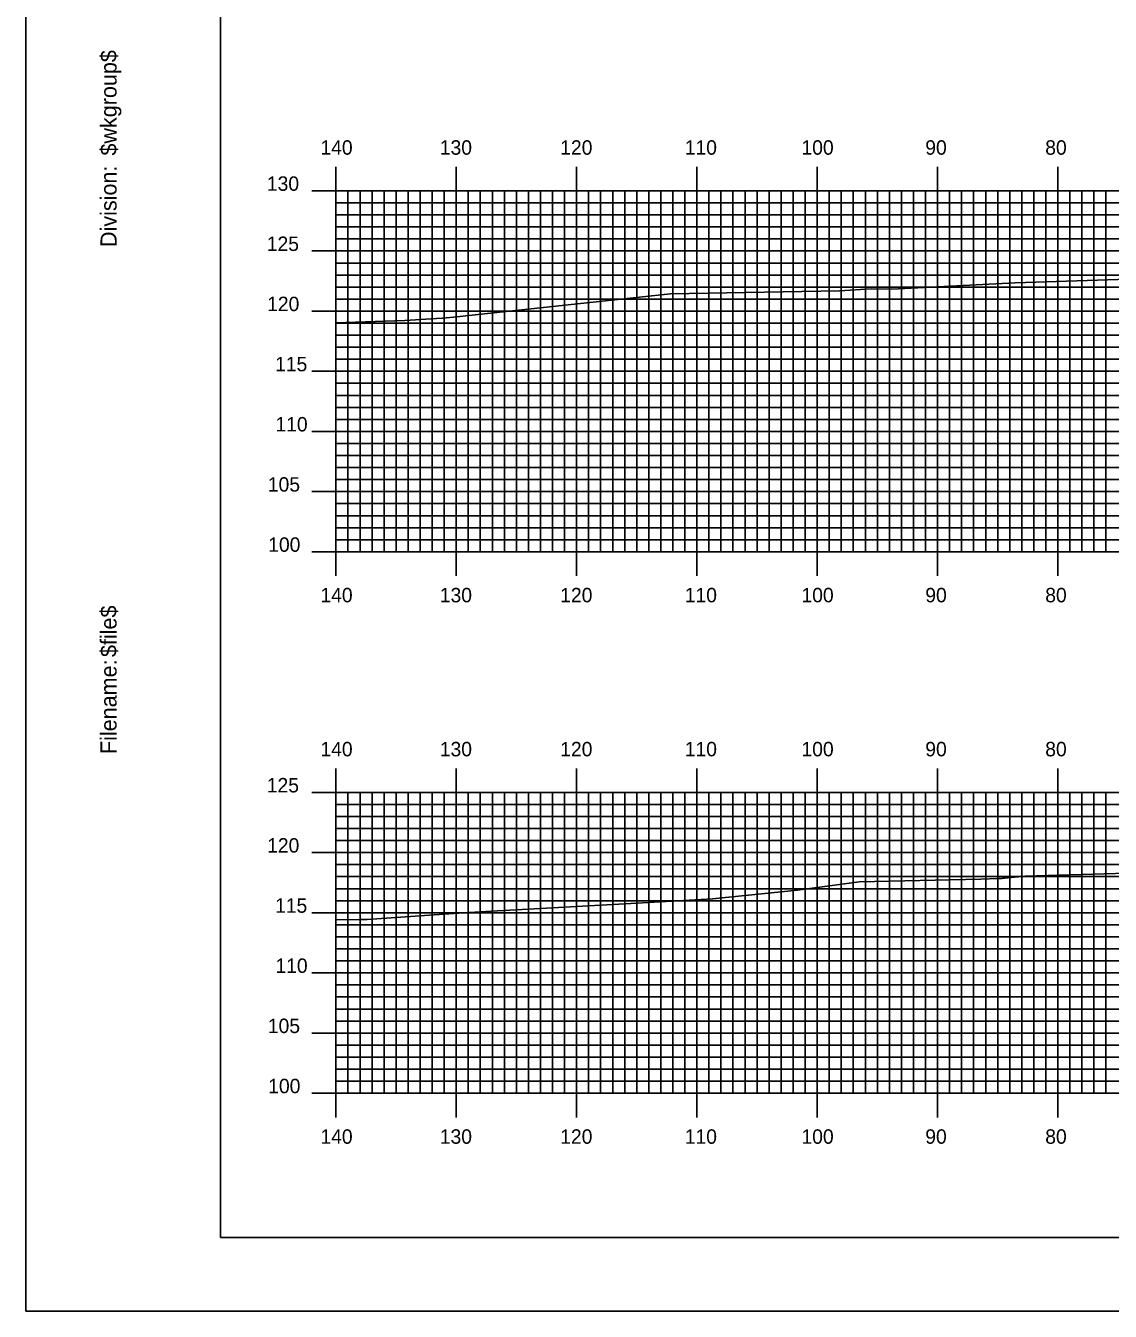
# Model space of a CAD drawing. Extents: x 1766907 to 1767250, y 442591 to 442811.
# Drawn here: x 1766906.6 to 1766996.8, y 442590.5 to 442697.4 of the extents above; entities that cross this region are included whole.
import ezdxf

# ---------------------------------------------------------------- set-up
doc = ezdxf.new("R2010")
doc.units = 0
for name, color, linetype in [('BORDER', 7, 'Continuous'), ('H_V ANNOTATION', 7, 'Continuous'), ('MAJOR', 7, 'Continuous'), ('MINOR', 7, 'Continuous'), ('PLOT BOUNDARY', 7, 'Continuous'), ('S_Roadway_Centerline', 7, 'Continuous')]:
    doc.layers.add(name, color=color, linetype=linetype)

msp = doc.modelspace()

# ---------------------------------------------------------------- linework, layer by layer
at = {"layer": 'BORDER'}
msp.add_lwpolyline([(1766922.82, 442596.67), (1767242.82, 442596.67), (1767242.82, 442806.67), (1766922.82, 442806.67)], close=True, dxfattribs=at)
at = {"layer": 'MAJOR'}
for p, q in [((1766932.42, 442685.67), (1766932.42, 442683.67)), ((1766942.42, 442685.67), (1766942.42, 442683.67)), ((1766952.42, 442685.67), (1766952.42, 442683.67)), ((1766962.42, 442685.67), (1766962.42, 442683.67)), ((1766972.42, 442685.67), (1766972.42, 442683.67)), ((1766982.42, 442685.67), (1766982.42, 442683.67)), ((1766992.42, 442685.67), (1766992.42, 442683.67)), ((1766930.42, 442683.67), (1766932.42, 442683.67)), ((1766932.42, 442683.67), (1767212.42, 442683.67)), ((1766932.42, 442653.67), (1766932.42, 442683.67)), ((1766932.42, 442653.67), (1766932.42, 442683.67)), ((1766932.42, 442683.67), (1767212.42, 442683.67)), ((1766942.42, 442653.67), (1766942.42, 442683.67)), ((1766952.42, 442653.67), (1766952.42, 442683.67)), ((1766962.42, 442653.67), (1766962.42, 442683.67)), ((1766972.42, 442653.67), (1766972.42, 442683.67)), ((1766982.42, 442653.67), (1766982.42, 442683.67)), ((1766992.42, 442653.67), (1766992.42, 442683.67)), ((1766930.42, 442678.67), (1766932.42, 442678.67)), ((1766932.42, 442678.67), (1767212.42, 442678.67)), ((1766930.42, 442673.67), (1766932.42, 442673.67)), ((1766932.42, 442673.67), (1767212.42, 442673.67)), ((1766930.42, 442668.67), (1766932.42, 442668.67)), ((1766932.42, 442668.67), (1767212.42, 442668.67)), ((1766930.42, 442663.67), (1766932.42, 442663.67)), ((1766932.42, 442663.67), (1767212.42, 442663.67)), ((1766930.42, 442658.67), (1766932.42, 442658.67)), ((1766932.42, 442658.67), (1767212.42, 442658.67)), ((1766930.42, 442653.67), (1766932.42, 442653.67)), ((1766932.42, 442653.67), (1767212.42, 442653.67)), ((1766932.42, 442653.67), (1767212.42, 442653.67)), ((1766932.42, 442651.66), (1766932.42, 442653.67)), ((1766942.42, 442651.66), (1766942.42, 442653.67)), ((1766952.42, 442651.66), (1766952.42, 442653.67)), ((1766962.42, 442651.66), (1766962.42, 442653.67)), ((1766972.42, 442651.66), (1766972.42, 442653.67)), ((1766982.42, 442651.66), (1766982.42, 442653.67)), ((1766992.42, 442651.66), (1766992.42, 442653.67)), ((1766932.42, 442635.67), (1766932.42, 442633.67)), ((1766942.42, 442635.67), (1766942.42, 442633.67)), ((1766952.42, 442635.67), (1766952.42, 442633.67)), ((1766962.42, 442635.67), (1766962.42, 442633.67)), ((1766972.42, 442635.67), (1766972.42, 442633.67)), ((1766982.42, 442635.67), (1766982.42, 442633.67)), ((1766992.42, 442635.67), (1766992.42, 442633.67)), ((1766930.42, 442633.67), (1766932.42, 442633.67)), ((1766932.42, 442633.67), (1767212.42, 442633.67)), ((1766932.42, 442608.67), (1766932.42, 442633.67)), ((1766932.42, 442608.67), (1766932.42, 442633.67)), ((1766932.42, 442633.67), (1767212.42, 442633.67)), ((1766942.42, 442608.67), (1766942.42, 442633.67)), ((1766952.42, 442608.67), (1766952.42, 442633.67)), ((1766962.42, 442608.67), (1766962.42, 442633.67)), ((1766972.42, 442608.67), (1766972.42, 442633.67)), ((1766982.42, 442608.67), (1766982.42, 442633.67)), ((1766992.42, 442608.67), (1766992.42, 442633.67)), ((1766930.42, 442628.67), (1766932.42, 442628.67)), ((1766932.42, 442628.67), (1767212.42, 442628.67)), ((1766930.42, 442623.67), (1766932.42, 442623.67)), ((1766932.42, 442623.67), (1767212.42, 442623.67)), ((1766930.42, 442618.67), (1766932.42, 442618.67)), ((1766932.42, 442618.67), (1767212.42, 442618.67)), ((1766930.42, 442613.67), (1766932.42, 442613.67)), ((1766932.42, 442613.67), (1767212.42, 442613.67)), ((1766930.42, 442608.67), (1766932.42, 442608.67)), ((1766932.42, 442608.67), (1767212.42, 442608.67)), ((1766932.42, 442608.67), (1767212.42, 442608.67)), ((1766932.42, 442606.66), (1766932.42, 442608.67)), ((1766942.42, 442606.66), (1766942.42, 442608.67)), ((1766952.42, 442606.66), (1766952.42, 442608.67)), ((1766962.42, 442606.66), (1766962.42, 442608.67)), ((1766972.42, 442606.66), (1766972.42, 442608.67)), ((1766982.42, 442606.66), (1766982.42, 442608.67)), ((1766992.42, 442606.66), (1766992.42, 442608.67))]:
    msp.add_line(p, q, dxfattribs=at)
at = {"layer": 'MINOR'}
for p, q in [((1766933.42, 442653.67), (1766933.42, 442683.67)), ((1766934.42, 442653.67), (1766934.42, 442683.67)), ((1766935.42, 442653.67), (1766935.42, 442683.67)), ((1766936.42, 442653.67), (1766936.42, 442683.67)), ((1766937.42, 442653.67), (1766937.42, 442683.67)), ((1766938.42, 442653.67), (1766938.42, 442683.67)), ((1766939.42, 442653.67), (1766939.42, 442683.67)), ((1766940.42, 442653.67), (1766940.42, 442683.67)), ((1766941.42, 442653.67), (1766941.42, 442683.67)), ((1766943.42, 442653.67), (1766943.42, 442683.67)), ((1766944.42, 442653.67), (1766944.42, 442683.67)), ((1766945.42, 442653.67), (1766945.42, 442683.67)), ((1766946.42, 442653.67), (1766946.42, 442683.67)), ((1766947.42, 442653.67), (1766947.42, 442683.67)), ((1766948.42, 442653.67), (1766948.42, 442683.67)), ((1766949.42, 442653.67), (1766949.42, 442683.67)), ((1766950.42, 442653.67), (1766950.42, 442683.67)), ((1766951.42, 442653.67), (1766951.42, 442683.67)), ((1766953.42, 442653.67), (1766953.42, 442683.67)), ((1766954.42, 442653.67), (1766954.42, 442683.67)), ((1766955.42, 442653.67), (1766955.42, 442683.67)), ((1766956.42, 442653.67), (1766956.42, 442683.67)), ((1766957.42, 442653.67), (1766957.42, 442683.67)), ((1766958.42, 442653.67), (1766958.42, 442683.67)), ((1766959.42, 442653.67), (1766959.42, 442683.67)), ((1766960.42, 442653.67), (1766960.42, 442683.67)), ((1766961.42, 442653.67), (1766961.42, 442683.67)), ((1766963.42, 442653.67), (1766963.42, 442683.67)), ((1766964.42, 442653.67), (1766964.42, 442683.67)), ((1766965.42, 442653.67), (1766965.42, 442683.67)), ((1766966.42, 442653.67), (1766966.42, 442683.67)), ((1766967.42, 442653.67), (1766967.42, 442683.67)), ((1766968.42, 442653.67), (1766968.42, 442683.67)), ((1766969.42, 442653.67), (1766969.42, 442683.67)), ((1766970.42, 442653.67), (1766970.42, 442683.67)), ((1766971.42, 442653.67), (1766971.42, 442683.67)), ((1766973.42, 442653.67), (1766973.42, 442683.67)), ((1766974.42, 442653.67), (1766974.42, 442683.67)), ((1766975.42, 442653.67), (1766975.42, 442683.67)), ((1766976.42, 442653.67), (1766976.42, 442683.67)), ((1766977.42, 442653.67), (1766977.42, 442683.67)), ((1766978.42, 442653.67), (1766978.42, 442683.67)), ((1766979.42, 442653.67), (1766979.42, 442683.67)), ((1766980.42, 442653.67), (1766980.42, 442683.67)), ((1766981.42, 442653.67), (1766981.42, 442683.67)), ((1766983.42, 442653.67), (1766983.42, 442683.67)), ((1766984.42, 442653.67), (1766984.42, 442683.67)), ((1766985.42, 442653.67), (1766985.42, 442683.67)), ((1766986.42, 442653.67), (1766986.42, 442683.67)), ((1766987.42, 442653.67), (1766987.42, 442683.67)), ((1766988.42, 442653.67), (1766988.42, 442683.67)), ((1766989.42, 442653.67), (1766989.42, 442683.67)), ((1766990.42, 442653.67), (1766990.42, 442683.67)), ((1766991.42, 442653.67), (1766991.42, 442683.67)), ((1766993.42, 442653.67), (1766993.42, 442683.67)), ((1766994.42, 442653.67), (1766994.42, 442683.67)), ((1766995.42, 442653.67), (1766995.42, 442683.67)), ((1766996.42, 442653.67), (1766996.42, 442683.67)), ((1766932.42, 442682.67), (1767212.42, 442682.67)), ((1766932.42, 442682.67), (1766934.43, 442682.67)), ((1766932.42, 442681.67), (1767212.42, 442681.67)), ((1766932.42, 442681.67), (1766934.43, 442681.67)), ((1766932.42, 442680.67), (1767212.42, 442680.67)), ((1766932.42, 442680.67), (1766934.43, 442680.67)), ((1766932.42, 442679.67), (1767212.42, 442679.67)), ((1766932.42, 442679.67), (1766934.43, 442679.67)), ((1766932.42, 442677.67), (1767212.42, 442677.67)), ((1766932.42, 442677.67), (1766934.43, 442677.67)), ((1766932.42, 442676.67), (1767212.42, 442676.67)), ((1766932.42, 442676.67), (1766934.43, 442676.67)), ((1766932.42, 442675.67), (1767212.42, 442675.67)), ((1766932.42, 442675.67), (1766934.43, 442675.67)), ((1766932.42, 442674.67), (1767212.42, 442674.67)), ((1766932.42, 442674.67), (1766934.43, 442674.67)), ((1766932.42, 442672.67), (1767212.42, 442672.67)), ((1766932.42, 442672.67), (1766934.43, 442672.67)), ((1766932.42, 442671.67), (1767212.42, 442671.67)), ((1766932.42, 442671.67), (1766934.43, 442671.67)), ((1766932.42, 442670.67), (1767212.42, 442670.67)), ((1766932.42, 442670.67), (1766934.43, 442670.67)), ((1766932.42, 442669.67), (1767212.42, 442669.67)), ((1766932.42, 442669.67), (1766934.43, 442669.67)), ((1766932.42, 442667.67), (1767212.42, 442667.67)), ((1766932.42, 442667.67), (1766934.43, 442667.67)), ((1766932.42, 442666.67), (1767212.42, 442666.67)), ((1766932.42, 442666.67), (1766934.43, 442666.67)), ((1766932.42, 442665.67), (1767212.42, 442665.67)), ((1766932.42, 442665.67), (1766934.43, 442665.67)), ((1766932.42, 442664.67), (1767212.42, 442664.67)), ((1766932.42, 442664.67), (1766934.43, 442664.67)), ((1766932.42, 442662.67), (1767212.42, 442662.67)), ((1766932.42, 442662.67), (1766934.43, 442662.67)), ((1766932.42, 442661.67), (1767212.42, 442661.67)), ((1766932.42, 442661.67), (1766934.43, 442661.67)), ((1766932.42, 442660.67), (1767212.42, 442660.67)), ((1766932.42, 442660.67), (1766934.43, 442660.67)), ((1766932.42, 442659.67), (1767212.42, 442659.67)), ((1766932.42, 442659.67), (1766934.43, 442659.67)), ((1766932.42, 442657.67), (1767212.42, 442657.67)), ((1766932.42, 442657.67), (1766934.43, 442657.67)), ((1766932.42, 442656.67), (1767212.42, 442656.67)), ((1766932.42, 442656.67), (1766934.43, 442656.67)), ((1766932.42, 442655.67), (1767212.42, 442655.67)), ((1766932.42, 442655.67), (1766934.43, 442655.67)), ((1766932.42, 442654.67), (1767212.42, 442654.67)), ((1766932.42, 442654.67), (1766934.43, 442654.67)), ((1766933.42, 442608.67), (1766933.42, 442633.67)), ((1766934.42, 442608.67), (1766934.42, 442633.67)), ((1766935.42, 442608.67), (1766935.42, 442633.67)), ((1766936.42, 442608.67), (1766936.42, 442633.67)), ((1766937.42, 442608.67), (1766937.42, 442633.67)), ((1766938.42, 442608.67), (1766938.42, 442633.67)), ((1766939.42, 442608.67), (1766939.42, 442633.67)), ((1766940.42, 442608.67), (1766940.42, 442633.67)), ((1766941.42, 442608.67), (1766941.42, 442633.67)), ((1766943.42, 442608.67), (1766943.42, 442633.67)), ((1766944.42, 442608.67), (1766944.42, 442633.67)), ((1766945.42, 442608.67), (1766945.42, 442633.67)), ((1766946.42, 442608.67), (1766946.42, 442633.67)), ((1766947.42, 442608.67), (1766947.42, 442633.67)), ((1766948.42, 442608.67), (1766948.42, 442633.67)), ((1766949.42, 442608.67), (1766949.42, 442633.67)), ((1766950.42, 442608.67), (1766950.42, 442633.67)), ((1766951.42, 442608.67), (1766951.42, 442633.67)), ((1766953.42, 442608.67), (1766953.42, 442633.67)), ((1766954.42, 442608.67), (1766954.42, 442633.67)), ((1766955.42, 442608.67), (1766955.42, 442633.67)), ((1766956.42, 442608.67), (1766956.42, 442633.67)), ((1766957.42, 442608.67), (1766957.42, 442633.67)), ((1766958.42, 442608.67), (1766958.42, 442633.67)), ((1766959.42, 442608.67), (1766959.42, 442633.67)), ((1766960.42, 442608.67), (1766960.42, 442633.67)), ((1766961.42, 442608.67), (1766961.42, 442633.67)), ((1766963.42, 442608.67), (1766963.42, 442633.67)), ((1766964.42, 442608.67), (1766964.42, 442633.67)), ((1766965.42, 442608.67), (1766965.42, 442633.67)), ((1766966.42, 442608.67), (1766966.42, 442633.67)), ((1766967.42, 442608.67), (1766967.42, 442633.67)), ((1766968.42, 442608.67), (1766968.42, 442633.67)), ((1766969.42, 442608.67), (1766969.42, 442633.67)), ((1766970.42, 442608.67), (1766970.42, 442633.67)), ((1766971.42, 442608.67), (1766971.42, 442633.67)), ((1766973.42, 442608.67), (1766973.42, 442633.67)), ((1766974.42, 442608.67), (1766974.42, 442633.67)), ((1766975.42, 442608.67), (1766975.42, 442633.67)), ((1766976.42, 442608.67), (1766976.42, 442633.67)), ((1766977.42, 442608.67), (1766977.42, 442633.67)), ((1766978.42, 442608.67), (1766978.42, 442633.67)), ((1766979.42, 442608.67), (1766979.42, 442633.67)), ((1766980.42, 442608.67), (1766980.42, 442633.67)), ((1766981.42, 442608.67), (1766981.42, 442633.67)), ((1766983.42, 442608.67), (1766983.42, 442633.67)), ((1766984.42, 442608.67), (1766984.42, 442633.67)), ((1766985.42, 442608.67), (1766985.42, 442633.67)), ((1766986.42, 442608.67), (1766986.42, 442633.67)), ((1766987.42, 442608.67), (1766987.42, 442633.67)), ((1766988.42, 442608.67), (1766988.42, 442633.67)), ((1766989.42, 442608.67), (1766989.42, 442633.67)), ((1766990.42, 442608.67), (1766990.42, 442633.67)), ((1766991.42, 442608.67), (1766991.42, 442633.67)), ((1766993.42, 442608.67), (1766993.42, 442633.67)), ((1766994.42, 442608.67), (1766994.42, 442633.67)), ((1766995.42, 442608.67), (1766995.42, 442633.67)), ((1766996.42, 442608.67), (1766996.42, 442633.67)), ((1766932.42, 442632.67), (1767212.42, 442632.67)), ((1766932.42, 442632.67), (1766934.43, 442632.67)), ((1766932.42, 442631.67), (1767212.42, 442631.67)), ((1766932.42, 442631.67), (1766934.43, 442631.67)), ((1766932.42, 442630.67), (1767212.42, 442630.67)), ((1766932.42, 442630.67), (1766934.43, 442630.67)), ((1766932.42, 442629.67), (1767212.42, 442629.67)), ((1766932.42, 442629.67), (1766934.43, 442629.67)), ((1766932.42, 442627.67), (1767212.42, 442627.67)), ((1766932.42, 442627.67), (1766934.43, 442627.67)), ((1766932.42, 442626.67), (1767212.42, 442626.67)), ((1766932.42, 442626.67), (1766934.43, 442626.67)), ((1766932.42, 442625.67), (1767212.42, 442625.67)), ((1766932.42, 442625.67), (1766934.43, 442625.67)), ((1766932.42, 442624.67), (1767212.42, 442624.67)), ((1766932.42, 442624.67), (1766934.43, 442624.67)), ((1766932.42, 442622.67), (1767212.42, 442622.67)), ((1766932.42, 442622.67), (1766934.43, 442622.67)), ((1766932.42, 442621.67), (1767212.42, 442621.67)), ((1766932.42, 442621.67), (1766934.43, 442621.67)), ((1766932.42, 442620.67), (1767212.42, 442620.67)), ((1766932.42, 442620.67), (1766934.43, 442620.67)), ((1766932.42, 442619.67), (1767212.42, 442619.67)), ((1766932.42, 442619.67), (1766934.43, 442619.67)), ((1766932.42, 442617.67), (1767212.42, 442617.67)), ((1766932.42, 442617.67), (1766934.43, 442617.67)), ((1766932.42, 442616.67), (1767212.42, 442616.67)), ((1766932.42, 442616.67), (1766934.43, 442616.67)), ((1766932.42, 442615.67), (1767212.42, 442615.67)), ((1766932.42, 442615.67), (1766934.43, 442615.67)), ((1766932.42, 442614.67), (1767212.42, 442614.67)), ((1766932.42, 442614.67), (1766934.43, 442614.67)), ((1766932.42, 442612.67), (1767212.42, 442612.67)), ((1766932.42, 442612.67), (1766934.43, 442612.67)), ((1766932.42, 442611.67), (1767212.42, 442611.67)), ((1766932.42, 442611.67), (1766934.43, 442611.67)), ((1766932.42, 442610.67), (1767212.42, 442610.67)), ((1766932.42, 442610.67), (1766934.43, 442610.67)), ((1766932.42, 442609.67), (1767212.42, 442609.67)), ((1766932.42, 442609.67), (1766934.43, 442609.67))]:
    msp.add_line(p, q, dxfattribs=at)
at = {"layer": 'PLOT BOUNDARY'}
msp.add_lwpolyline([(1766906.64, 442590.55), (1767246.64, 442590.55), (1767246.64, 442810.55), (1766906.64, 442810.55)], close=True, dxfattribs=at)
at = {"layer": 'S_Roadway_Centerline'}
for points in [[(1766932.42, 442672.69), (1766938.15, 442672.9), (1766940.77, 442673.06), (1766941.29, 442673.08), (1766942.18, 442673.18), (1766960.22, 442675.1), (1766974.26, 442675.37), (1766976.91, 442675.53), (1766978.63, 442675.5), (1766988.86, 442676.02), (1766998.27, 442676.33)], [(1766932.42, 442623.1), (1766932.48, 442623.09), (1766934.5, 442623.11), (1766935.01, 442623.11), (1766937.81, 442623.3), (1766940.58, 442623.49), (1766943.04, 442623.65), (1766945.33, 442623.79), (1766947.41, 442623.92), (1766956.92, 442624.43), (1766961.81, 442624.71), (1766963.72, 442624.82), (1766970.77, 442625.54), (1766975.9, 442626.23), (1766986.01, 442626.47), (1766987.49, 442626.51), (1766987.59, 442626.52), (1766987.68, 442626.52), (1766987.76, 442626.53), (1766987.84, 442626.54), (1766987.9, 442626.54), (1766987.96, 442626.55), (1766988.02, 442626.55), (1766989.71, 442626.71), (1767024.47, 442627.74)]]:
    msp.add_lwpolyline(points, dxfattribs=at)

# ---------------------------------------------------------------- texts
at = {"layer": 'BORDER'}
for s, p in [('$wkgroup$', (1766914.19, 442686.6)), ('Division:', (1766914.19, 442679)), ('$file$', (1766914.19, 442644.92)), ('Filename:', (1766914.19, 442636.86))]:
    msp.add_text(s, height=1.339, rotation=90, dxfattribs=at).set_placement(p)
at = {"layer": 'H_V ANNOTATION'}
for s, p in [('140', (1766931.13, 442686.67)), ('130', (1766941.05, 442686.67)), ('120', (1766951.06, 442686.67)), ('110', (1766961.41, 442686.67)), ('100', (1766971.11, 442686.67)), ('90', (1766981.4, 442686.67)), ('80', (1766991.37, 442686.67)), ('130', (1766926.68, 442683.67)), ('125', (1766926.67, 442678.67)), ('120', (1766926.7, 442673.67)), ('115', (1766927.36, 442668.67)), ('110', (1766927.39, 442663.67)), ('105', (1766926.76, 442658.67)), ('100', (1766926.79, 442653.67)), ('140', (1766931.13, 442649.47)), ('130', (1766941.05, 442649.47)), ('120', (1766951.06, 442649.47)), ('110', (1766961.41, 442649.47)), ('100', (1766971.11, 442649.47)), ('90', (1766981.4, 442649.47)), ('80', (1766991.37, 442649.47)), ('140', (1766931.13, 442636.67)), ('130', (1766941.05, 442636.67)), ('120', (1766951.06, 442636.67)), ('110', (1766961.41, 442636.67)), ('100', (1766971.11, 442636.67)), ('90', (1766981.4, 442636.67)), ('80', (1766991.37, 442636.67)), ('125', (1766926.67, 442633.67)), ('120', (1766926.7, 442628.67)), ('115', (1766927.36, 442623.67)), ('110', (1766927.39, 442618.67)), ('105', (1766926.76, 442613.67)), ('100', (1766926.79, 442608.67)), ('140', (1766931.13, 442604.47)), ('130', (1766941.05, 442604.47)), ('120', (1766951.06, 442604.47)), ('110', (1766961.41, 442604.47)), ('100', (1766971.11, 442604.47)), ('90', (1766981.4, 442604.47)), ('80', (1766991.37, 442604.47))]:
    msp.add_text(s, height=1.2, dxfattribs=at).set_placement(p)
at = {"layer": 'MAJOR'}
for p in [(1766932.41, 442653.67), (1766932.41, 442608.67)]:
    msp.add_text('-', height=0.012, dxfattribs=at).set_placement(p)

doc.saveas('drawing.dxf')
